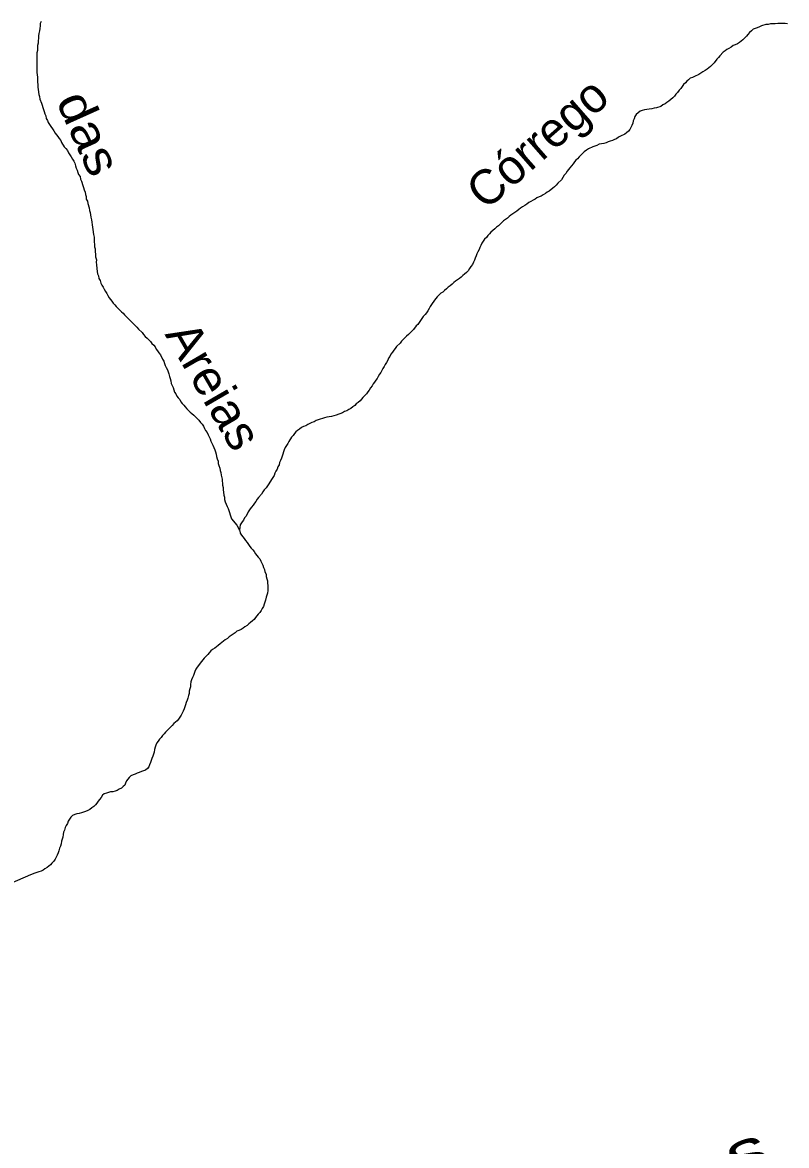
# Model space of a CAD drawing. Extents: x 785.9 to 812.4, y 7674.9 to 7703.1.
# Drawn here: x 800.201 to 801.963, y 7693.236 to 7695.824 of the extents above; entities that cross this region are included whole.
import ezdxf
from ezdxf.enums import TextEntityAlignment as Align

# ---------------------------------------------------------------- set-up
doc = ezdxf.new("R2010")
doc.units = 0
doc.header["$LTSCALE"] = 0.04
doc.layers.add('61', color=7, linetype='Continuous')
doc.layers.add('7', color=7, linetype='Continuous', lineweight=25)

msp = doc.modelspace()

# ---------------------------------------------------------------- linework, layer by layer
at = {"layer": '7'}
for points in [[(800.2443, 7695.8268), (800.2426, 7695.8219), (800.2426, 7695.8162), (800.2418, 7695.8106), (800.241, 7695.8049), (800.2394, 7695.7992), (800.2386, 7695.7936), (800.2386, 7695.7879), (800.2378, 7695.7823), (800.2378, 7695.7766), (800.2362, 7695.7709), (800.2362, 7695.7596), (800.2345, 7695.7547), (800.2345, 7695.7094), (800.2354, 7695.7038), (800.2362, 7695.6981), (800.2362, 7695.6868), (800.237, 7695.6811), (800.237, 7695.6754), (800.2378, 7695.6698), (800.2394, 7695.6585), (800.241, 7695.6536), (800.2418, 7695.6479), (800.2451, 7695.6382), (800.2467, 7695.6334), (800.2483, 7695.6285), (800.2499, 7695.6237), (800.2515, 7695.6188), (800.2532, 7695.614), (800.2556, 7695.6091), (800.2564, 7695.6034), (800.2588, 7695.5986), (800.2604, 7695.5937), (800.2637, 7695.5889), (800.2734, 7695.5743), (800.2766, 7695.5694), (800.2831, 7695.5614), (800.2863, 7695.5573), (800.2896, 7695.5525), (800.2912, 7695.5476), (800.2977, 7695.5379), (800.3017, 7695.5338), (800.3049, 7695.529), (800.3074, 7695.5241), (800.3106, 7695.5193), (800.3138, 7695.5144), (800.3171, 7695.5096), (800.3195, 7695.5047), (800.3219, 7695.4999), (800.3236, 7695.4942), (800.3252, 7695.4885), (800.3276, 7695.4837), (800.3292, 7695.4788), (800.3308, 7695.474), (800.3341, 7695.4691), (800.3349, 7695.4635), (800.3373, 7695.4586), (800.3405, 7695.4489), (800.3422, 7695.444), (800.3438, 7695.4384), (800.3462, 7695.4335), (800.347, 7695.4278), (800.3486, 7695.423), (800.3486, 7695.4173), (800.3511, 7695.4125), (800.3519, 7695.4068), (800.3551, 7695.3971), (800.3559, 7695.3914), (800.3575, 7695.3866), (800.3583, 7695.3809), (800.3592, 7695.3753), (800.3608, 7695.3696), (800.3616, 7695.3639), (800.3624, 7695.3583), (800.3632, 7695.3526), (800.364, 7695.3469), (800.3648, 7695.3356), (800.3664, 7695.3299), (800.3664, 7695.3186), (800.3672, 7695.3129), (800.3672, 7695.3073), (800.3689, 7695.3024), (800.3689, 7695.296), (800.3697, 7695.2903), (800.3697, 7695.2846), (800.3721, 7695.2773), (800.3713, 7695.2717), (800.3721, 7695.266), (800.3729, 7695.2571), (800.3737, 7695.2506), (800.3745, 7695.245), (800.377, 7695.2401), (800.3778, 7695.2345), (800.3802, 7695.2296), (800.3818, 7695.2239), (800.3842, 7695.2191), (800.3875, 7695.2142), (800.3899, 7695.2094), (800.3931, 7695.2045), (800.3956, 7695.1997), (800.398, 7695.1948)], [(801.9653, 7695.8211), (801.9596, 7695.8219), (801.9426, 7695.8219), (801.937, 7695.8211), (801.9257, 7695.8211), (801.9208, 7695.8195), (801.9151, 7695.8195), (801.9054, 7695.8162), (801.9006, 7695.8146), (801.8957, 7695.8122), (801.886, 7695.809), (801.882, 7695.8049), (801.8779, 7695.8009), (801.8739, 7695.7968), (801.8706, 7695.7928), (801.8666, 7695.7887), (801.8625, 7695.7847), (801.8585, 7695.7814), (801.8545, 7695.7782), (801.8496, 7695.775), (801.8447, 7695.7725), (801.8399, 7695.7709), (801.835, 7695.7677), (801.8302, 7695.7645), (801.8253, 7695.762), (801.8213, 7695.7588), (801.8172, 7695.7556), (801.8091, 7695.7475), (801.8059, 7695.7434), (801.8027, 7695.7394), (801.7962, 7695.7313), (801.7921, 7695.7272), (801.7881, 7695.7232), (801.7841, 7695.7199), (801.78, 7695.7167), (801.7752, 7695.7135), (801.7703, 7695.7102), (801.7654, 7695.7078), (801.7606, 7695.7046), (801.7509, 7695.6997), (801.746, 7695.6973), (801.7412, 7695.6957), (801.7371, 7695.6924), (801.7331, 7695.6892), (801.7298, 7695.6852), (801.7258, 7695.6811), (801.7226, 7695.6771), (801.7193, 7695.6722), (801.7153, 7695.6682), (801.712, 7695.6633), (801.708, 7695.6593), (801.7048, 7695.6544), (801.7007, 7695.6504), (801.6959, 7695.6471), (801.6918, 7695.6431), (801.687, 7695.6398), (801.6829, 7695.6366), (801.6781, 7695.6342), (801.6732, 7695.6309), (801.6635, 7695.6277), (801.6578, 7695.6269), (801.6522, 7695.6253), (801.6465, 7695.6245), (801.6408, 7695.6237)], [(801.6408, 7695.6237), (801.6352, 7695.6229), (801.6303, 7695.6212), (801.6255, 7695.6196), (801.6206, 7695.6164), (801.6166, 7695.6123), (801.6133, 7695.6075), (801.6117, 7695.6026), (801.6093, 7695.5978), (801.6085, 7695.5921), (801.606, 7695.5872), (801.6044, 7695.5824), (801.602, 7695.5775), (801.5988, 7695.5735), (801.5939, 7695.5703), (801.5899, 7695.567), (801.5802, 7695.5622), (801.5753, 7695.5597), (801.5713, 7695.5565), (801.5664, 7695.5549), (801.5615, 7695.5525), (801.5567, 7695.5508), (801.5518, 7695.5492), (801.547, 7695.5468), (801.5421, 7695.5452), (801.5365, 7695.5444), (801.5308, 7695.5436), (801.5259, 7695.5411), (801.5211, 7695.5395), (801.5162, 7695.5379), (801.5065, 7695.533), (801.5017, 7695.5298), (801.4968, 7695.5266), (801.4887, 7695.5185), (801.4847, 7695.5144), (801.4814, 7695.5104), (801.4774, 7695.5071), (801.4742, 7695.5031), (801.4709, 7695.4982), (801.4669, 7695.4942), (801.4636, 7695.4893), (801.4604, 7695.4853), (801.4572, 7695.4813), (801.4539, 7695.4764), (801.4507, 7695.4724), (801.4475, 7695.4667), (801.4442, 7695.4618), (801.4361, 7695.4537), (801.4321, 7695.4497), (801.428, 7695.4456), (801.424, 7695.4424), (801.4159, 7695.4359), (801.411, 7695.4335), (801.407, 7695.4303), (801.4021, 7695.427), (801.3973, 7695.4238), (801.3924, 7695.4222), (801.3876, 7695.4206), (801.3835, 7695.4173), (801.3787, 7695.4149), (801.3738, 7695.4117), (801.369, 7695.4092), (801.3641, 7695.406), (801.3593, 7695.4028), (801.3544, 7695.3995), (801.3495, 7695.3963), (801.3455, 7695.3931), (801.3415, 7695.3898), (801.3366, 7695.3866), (801.3317, 7695.3833), (801.3277, 7695.3801), (801.3237, 7695.3769), (801.3196, 7695.3736), (801.3148, 7695.3704), (801.3107, 7695.3672), (801.3067, 7695.3631), (801.3026, 7695.3599), (801.2986, 7695.3558), (801.2945, 7695.3526), (801.2905, 7695.3486), (801.2856, 7695.3453), (801.2816, 7695.3413), (801.2783, 7695.3372), (801.2743, 7695.3332), (801.2711, 7695.3291), (801.267, 7695.3251), (801.2638, 7695.3202), (801.2605, 7695.3154), (801.2581, 7695.3105), (801.2557, 7695.3057), (801.2541, 7695.3008), (801.2516, 7695.296), (801.2492, 7695.2911), (801.2476, 7695.2862), (801.2452, 7695.2814), (801.2435, 7695.2765), (801.2411, 7695.2717), (801.2387, 7695.2668), (801.2355, 7695.262), (801.2322, 7695.2571), (801.229, 7695.2523)], [(801.229, 7695.2523), (801.2249, 7695.2482), (801.2209, 7695.2442), (801.2168, 7695.2409), (801.2128, 7695.2377), (801.2088, 7695.2345), (801.2047, 7695.2312), (801.1999, 7695.228), (801.1958, 7695.2248), (801.1918, 7695.2215), (801.1877, 7695.2175), (801.1829, 7695.2142), (801.1788, 7695.2102), (801.1748, 7695.207), (801.1707, 7695.2029), (801.1659, 7695.2005), (801.1578, 7695.1924), (801.1545, 7695.1883), (801.1513, 7695.1843), (801.1448, 7695.1746), (801.1416, 7695.1697), (801.1392, 7695.1649), (801.1359, 7695.16), (801.1327, 7695.1552), (801.1295, 7695.1511), (801.1254, 7695.1471), (801.1222, 7695.1422), (801.1189, 7695.1374), (801.1157, 7695.1333), (801.1133, 7695.1285), (801.1092, 7695.1252), (801.1028, 7695.1171), (801.0995, 7695.1131), (801.0914, 7695.105), (801.0866, 7695.1018), (801.0833, 7695.0977), (801.0752, 7695.0896), (801.072, 7695.0856), (801.0639, 7695.0775), (801.0607, 7695.0734), (801.0574, 7695.0694), (801.0542, 7695.0645), (801.051, 7695.0597), (801.0485, 7695.0548), (801.0453, 7695.0508), (801.0437, 7695.0459), (801.0405, 7695.0411), (801.038, 7695.0362), (801.0356, 7695.0314), (801.0324, 7695.0273), (801.0299, 7695.0225), (801.0275, 7695.0176), (801.0243, 7695.0136), (801.0218, 7695.0087), (801.0194, 7695.0039), (801.0162, 7694.9998), (801.0129, 7694.9958), (801.0097, 7694.9917), (801.0073, 7694.9869), (801.004, 7694.982), (801.0008, 7694.9772), (800.9976, 7694.9731), (800.9943, 7694.9683), (800.9862, 7694.9602), (800.983, 7694.9561), (800.9798, 7694.9521), (800.9757, 7694.9488), (800.9709, 7694.9456), (800.9676, 7694.9416), (800.9628, 7694.9383), (800.9587, 7694.9351), (800.9539, 7694.9327), (800.949, 7694.9294), (800.9442, 7694.9278), (800.9393, 7694.9246), (800.9247, 7694.9197), (800.9191, 7694.9181), (800.9142, 7694.9165), (800.9086, 7694.9157), (800.9029, 7694.9149), (800.898, 7694.9132), (800.8835, 7694.9084), (800.8786, 7694.9068), (800.8738, 7694.9043), (800.8689, 7694.9027), (800.8592, 7694.8979), (800.8544, 7694.8946), (800.8495, 7694.893), (800.8446, 7694.8906), (800.8398, 7694.8873), (800.8357, 7694.8841), (800.8317, 7694.8809), (800.8285, 7694.8768), (800.8252, 7694.8728), (800.822, 7694.8687), (800.8155, 7694.859), (800.8131, 7694.8542), (800.8098, 7694.8493), (800.8074, 7694.8445), (800.805, 7694.8396), (800.8034, 7694.8347)], [(800.398, 7695.1948), (800.4012, 7695.19), (800.4045, 7695.1859), (800.4077, 7695.1819), (800.4109, 7695.1778), (800.4142, 7695.1738), (800.4174, 7695.1697), (800.4215, 7695.1657), (800.4296, 7695.1576), (800.4336, 7695.1544), (800.4368, 7695.1503), (800.4449, 7695.1422), (800.449, 7695.1382), (800.4611, 7695.126), (800.4652, 7695.122), (800.4692, 7695.1179), (800.4773, 7695.1099), (800.4805, 7695.105), (800.4846, 7695.101), (800.4886, 7695.0969), (800.4927, 7695.0929), (800.4967, 7695.0888), (800.4999, 7695.0848), (800.504, 7695.0807), (800.5072, 7695.0767), (800.5097, 7695.0718), (800.5129, 7695.0678), (800.5161, 7695.0629), (800.5194, 7695.0581), (800.5242, 7695.0484), (800.5275, 7695.0435), (800.5291, 7695.0386), (800.5307, 7695.0338), (800.5331, 7695.0289), (800.5355, 7695.0241), (800.5372, 7695.0192), (800.5388, 7695.0144), (800.5404, 7695.0087), (800.542, 7695.0039), (800.5436, 7694.9982), (800.5445, 7694.9925), (800.5469, 7694.9877), (800.5485, 7694.9828), (800.5501, 7694.978), (800.5517, 7694.9723), (800.555, 7694.9683), (800.5574, 7694.9634), (800.5606, 7694.9594), (800.5639, 7694.9553), (800.5663, 7694.9505), (800.5695, 7694.9464), (800.5736, 7694.9424), (800.5768, 7694.9383), (800.5801, 7694.9343), (800.5881, 7694.9262), (800.5922, 7694.9229), (800.5962, 7694.9197), (800.6003, 7694.9157), (800.6084, 7694.9076), (800.6116, 7694.9027), (800.6157, 7694.8987), (800.6189, 7694.8938), (800.6213, 7694.889), (800.6237, 7694.8841), (800.627, 7694.8792), (800.6294, 7694.8744), (800.6318, 7694.8695), (800.6343, 7694.8647), (800.6359, 7694.8598), (800.6383, 7694.855), (800.6407, 7694.8501), (800.6424, 7694.8445), (800.6448, 7694.8396), (800.6464, 7694.8347), (800.648, 7694.8299), (800.6488, 7694.8242), (800.6504, 7694.8186), (800.6529, 7694.8137), (800.6529, 7694.808), (800.6545, 7694.8032), (800.6561, 7694.7975), (800.6569, 7694.7919), (800.6585, 7694.787), (800.6593, 7694.7813), (800.6618, 7694.7716), (800.6626, 7694.7579), (800.6642, 7694.753), (800.6642, 7694.7474), (800.665, 7694.7417), (800.6658, 7694.7352), (800.6674, 7694.7304), (800.6674, 7694.7247), (800.6691, 7694.7198), (800.6707, 7694.7142), (800.6731, 7694.7093), (800.6755, 7694.7045), (800.6771, 7694.6996), (800.6788, 7694.6948), (800.6804, 7694.6899), (800.6836, 7694.6802), (800.6955, 7694.666)], [(800.8034, 7694.8347), (800.8018, 7694.8299), (800.7985, 7694.8202), (800.7961, 7694.8153), (800.7937, 7694.8105), (800.7929, 7694.8048), (800.7904, 7694.8), (800.7888, 7694.7951), (800.7856, 7694.7902), (800.7831, 7694.7854), (800.7815, 7694.7805), (800.7783, 7694.7757), (800.7759, 7694.7708), (800.7694, 7694.7611), (800.7662, 7694.7563), (800.7629, 7694.7522), (800.7589, 7694.7474), (800.7556, 7694.7425), (800.7524, 7694.7376), (800.7459, 7694.7296), (800.7427, 7694.7255), (800.7395, 7694.7207), (800.7362, 7694.7166), (800.733, 7694.7118), (800.7297, 7694.7077), (800.7265, 7694.7037), (800.7217, 7694.6964), (800.7168, 7694.6867), (800.7136, 7694.6826), (800.7111, 7694.6778), (800.7081, 7694.6733), (800.7036, 7694.6666)], [(800.702, 7694.6543), (800.7022, 7694.6527), (800.703, 7694.6478), (800.7063, 7694.643), (800.7095, 7694.6389), (800.7128, 7694.6349), (800.716, 7694.6308), (800.7192, 7694.626), (800.7225, 7694.6211), (800.7257, 7694.6171), (800.7289, 7694.613), (800.7322, 7694.609), (800.7354, 7694.6049), (800.7386, 7694.6001), (800.7419, 7694.596), (800.7451, 7694.592), (800.7484, 7694.588), (800.7508, 7694.5831), (800.7532, 7694.5782), (800.7556, 7694.5734), (800.7573, 7694.5685), (800.7597, 7694.5637), (800.7605, 7694.558), (800.7629, 7694.5532), (800.7629, 7694.5475), (800.7645, 7694.5426), (800.7662, 7694.5378), (800.7662, 7694.5321), (800.767, 7694.5265), (800.767, 7694.5208), (800.767, 7694.5151), (800.7662, 7694.5095), (800.7645, 7694.5046), (800.7629, 7694.4998), (800.7621, 7694.4933), (800.7605, 7694.4884), (800.7589, 7694.4836), (800.7573, 7694.4787), (800.754, 7694.4739), (800.7516, 7694.469), (800.7484, 7694.465), (800.7451, 7694.4609), (800.7419, 7694.4569), (800.7386, 7694.4528), (800.7354, 7694.4488), (800.7314, 7694.4455), (800.7273, 7694.4415), (800.7233, 7694.4383), (800.7192, 7694.435), (800.7144, 7694.4318), (800.7103, 7694.4286), (800.7055, 7694.4253), (800.7006, 7694.4229), (800.6958, 7694.4213), (800.6917, 7694.418), (800.6869, 7694.4148), (800.6828, 7694.4116), (800.678, 7694.4083), (800.6739, 7694.4051), (800.6691, 7694.4019), (800.665, 7694.3986), (800.661, 7694.3954), (800.6569, 7694.3921), (800.6529, 7694.3889), (800.6488, 7694.3857), (800.6448, 7694.3824), (800.6399, 7694.3792), (800.6359, 7694.376), (800.6318, 7694.3719), (800.6286, 7694.3679), (800.6246, 7694.3638), (800.6205, 7694.3598), (800.6173, 7694.3557), (800.614, 7694.3517), (800.6108, 7694.3476)], [(800.6955, 7694.666), (800.702, 7694.6543), (800.702, 7694.6543)], [(800.7036, 7694.6666), (800.702, 7694.6543), (800.702, 7694.6543)], [(800.6108, 7694.3476), (800.6076, 7694.3428), (800.6043, 7694.3387), (800.6011, 7694.3339), (800.5987, 7694.329), (800.597, 7694.3242), (800.5954, 7694.3193), (800.5938, 7694.3145), (800.5914, 7694.3096), (800.5898, 7694.3048), (800.589, 7694.2991), (800.589, 7694.2934), (800.5873, 7694.2886), (800.5857, 7694.2837), (800.5857, 7694.2781), (800.5841, 7694.2732), (800.5825, 7694.2675), (800.5809, 7694.2627), (800.5792, 7694.257), (800.5776, 7694.2522), (800.576, 7694.2473), (800.5744, 7694.2425), (800.572, 7694.2376), (800.5695, 7694.2327), (800.5671, 7694.2279), (800.5639, 7694.2238), (800.5614, 7694.219), (800.5582, 7694.2149), (800.5542, 7694.2117), (800.5501, 7694.2085), (800.5469, 7694.2044), (800.5428, 7694.2004), (800.5388, 7694.1963), (800.5347, 7694.1931), (800.5315, 7694.189), (800.5283, 7694.185), (800.5242, 7694.181), (800.521, 7694.1769), (800.5177, 7694.1729), (800.5145, 7694.168), (800.5113, 7694.164), (800.5088, 7694.1591), (800.5072, 7694.1543), (800.5056, 7694.1486), (800.5048, 7694.1429), (800.5032, 7694.1381), (800.5016, 7694.1332), (800.4999, 7694.1284), (800.4983, 7694.1235), (800.4967, 7694.1187), (800.4943, 7694.1138), (800.4927, 7694.1089), (800.4894, 7694.1049), (800.4854, 7694.1017), (800.4805, 7694.1), (800.4757, 7694.0984), (800.4708, 7694.096), (800.466, 7694.0944), (800.4611, 7694.092), (800.4563, 7694.0903), (800.4514, 7694.0879), (800.4474, 7694.0847), (800.4441, 7694.0806), (800.4409, 7694.0766), (800.4393, 7694.0717), (800.4376, 7694.0669), (800.4336, 7694.0636), (800.4296, 7694.0596), (800.4247, 7694.0572), (800.4198, 7694.0547), (800.415, 7694.0531), (800.4101, 7694.0515), (800.4045, 7694.0515), (800.3996, 7694.0499), (800.3948, 7694.0483), (800.3899, 7694.0466), (800.3859, 7694.0434), (800.3826, 7694.0385), (800.3794, 7694.0337), (800.3761, 7694.0296), (800.3729, 7694.0256), (800.3697, 7694.0216), (800.3656, 7694.0175), (800.3616, 7694.0143), (800.3567, 7694.011), (800.3519, 7694.0086), (800.347, 7694.0062), (800.3422, 7694.0046), (800.3373, 7694.0029), (800.3325, 7694.0013), (800.3268, 7694.0005), (800.3219, 7693.9989), (800.3171, 7693.9965), (800.313, 7693.9932), (800.3098, 7693.9884), (800.3066, 7693.9835), (800.3049, 7693.9787), (800.3025, 7693.9738), (800.3001, 7693.969), (800.2985, 7693.9633), (800.296, 7693.9584)], [(800.296, 7693.9584), (800.2952, 7693.9528), (800.2944, 7693.9471), (800.2928, 7693.9423), (800.2912, 7693.9374), (800.2904, 7693.9317), (800.2888, 7693.9261), (800.2871, 7693.9212), (800.2855, 7693.9156), (800.2839, 7693.9107), (800.2815, 7693.9058), (800.2791, 7693.901), (800.2766, 7693.8961), (800.2734, 7693.8913), (800.2693, 7693.8872), (800.2661, 7693.8832), (800.2621, 7693.88), (800.258, 7693.8767), (800.2532, 7693.8743), (800.2491, 7693.8711), (800.2443, 7693.8686), (800.2394, 7693.867), (800.2345, 7693.8654), (800.2297, 7693.8638), (800.22, 7693.8605), (800.1722, 7693.8395)]]:
    msp.add_lwpolyline(points, dxfattribs=at)

# ---------------------------------------------------------------- texts
at = {"layer": '61'}
msp.add_text('Córrego', height=0.08, rotation=41.237, dxfattribs=at).set_placement((801.4147, 7695.5169), align=Align.CENTER)
for s, height, rotation, width, p in [('das', 0.08, 294.155, 1.15, (800.3185, 7695.5533)), ('Areias', 0.08, 300.107, 1.05, (800.6084, 7694.968)), ('s', 0.1, 21.084, 1.4, (801.8875, 7693.1756))]:
    msp.add_text(s, height=height, rotation=rotation, dxfattribs=dict(at, width=width)).set_placement(p, align=Align.CENTER)

doc.saveas('drawing.dxf')
